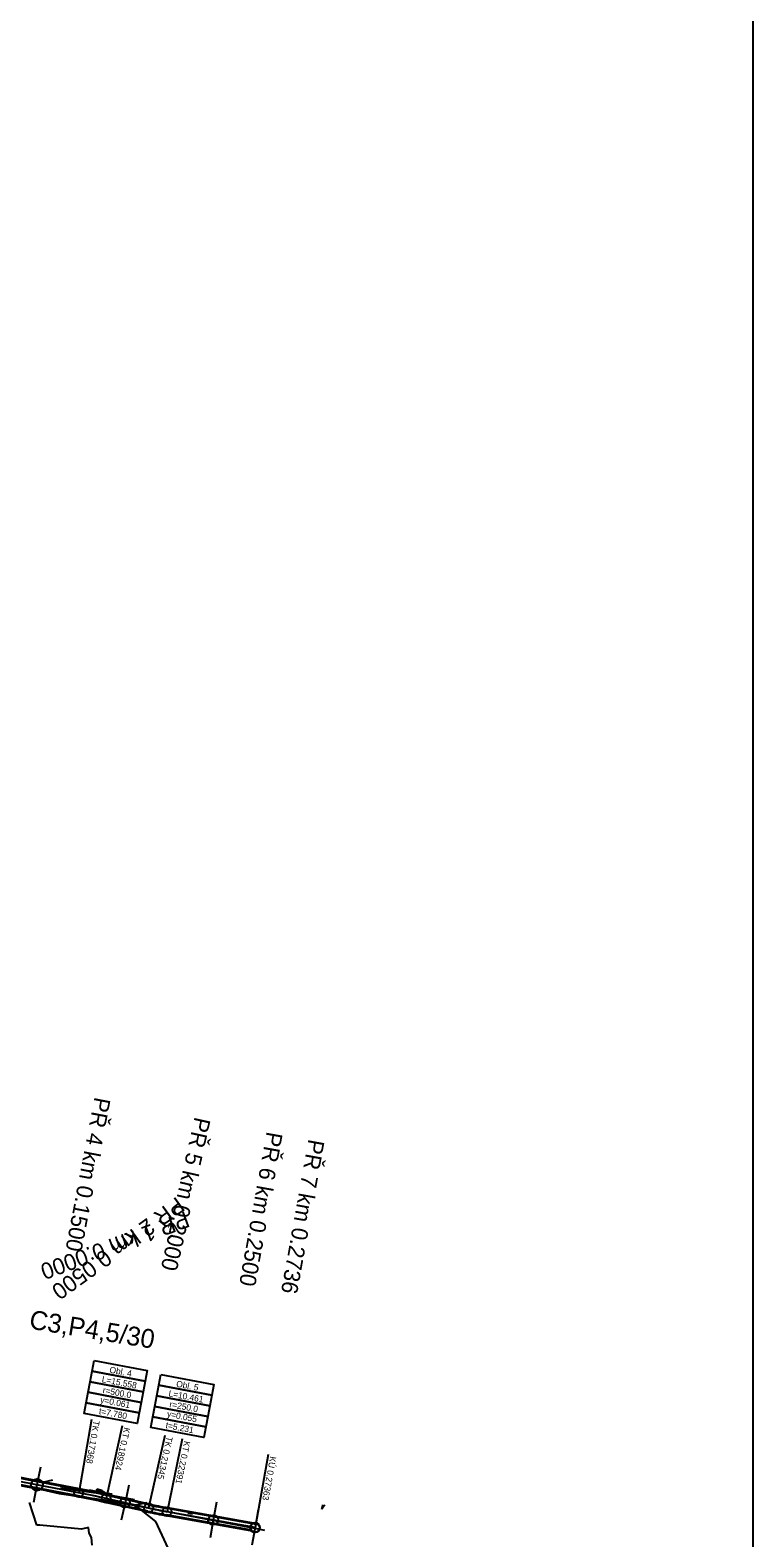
# Model space of a CAD drawing. Extents: x -549394 to -546608, y -1037055 to -1033629.
# Drawn here: x -547010 to -546608, y -1035815 to -1034976 of the extents above; entities that cross this region are included whole.
import ezdxf

# ---------------------------------------------------------------- set-up
doc = ezdxf.new("R2010")
doc.units = 0
for name, color, linetype in [('hlavni_vrst', 7, 'Continuous'), ('hrana_L', 7, 'Continuous'), ('norm_vrst', 7, 'Continuous'), ('POLYGONY_SITUACE_PO', 7, 'Continuous'), ('ram', 7, 'Continuous'), ('u_sirka_0_5m', 7, 'Continuous'), ('u_sirka_1_0m', 7, 'Continuous'), ('x_navrh_C3', 7, 'Continuous'), ('x_osa_C3', 7, 'Continuous'), ('x_popis_oblouky_C3', 7, 'Continuous'), ('x_popis_pricne_rezy_C3', 7, 'Continuous'), ('x_popis_velky_C3', 7, 'Continuous')]:
    doc.layers.add(name, color=color, linetype=linetype)

msp = doc.modelspace()

# ---------------------------------------------------------------- linework, layer by layer
at = {"layer": 'hlavni_vrst'}
for p, q in [((-547006.35, -1035807.78), (-547010.39, -1035795.15)), ((-547004.64, -1035807.74), (-547006.35, -1035807.78)), ((-546981.44, -1035810.13), (-547004.64, -1035807.74)), ((-546977.6, -1035809.03), (-546981.44, -1035810.13)), ((-546977.2, -1035812.22), (-546977.6, -1035809.03)), ((-546975.87, -1035814.66), (-546977.2, -1035812.22)), ((-546975.65, -1035818.99), (-546975.87, -1035814.66))]:
    msp.add_line(p, q, dxfattribs=at)
at = {"layer": 'hrana_L'}
for p, q in [((-547014.03, -1035785.6), (-546993.98, -1035790.12)), ((-546968.09, -1035790.83), (-546993.14, -1035787.24)), ((-546993.98, -1035790.12), (-546968.85, -1035793.8)), ((-546968.85, -1035793.8), (-546952.42, -1035796.77)), ((-546952.1, -1035793.78), (-546968.09, -1035790.83)), ((-546952.42, -1035796.77), (-546883.17, -1035809.84)), ((-546883.17, -1035809.84), (-546879.7, -1035810.51))]:
    msp.add_line(p, q, dxfattribs=at)
at = {"layer": 'norm_vrst'}
for p, q in [((-547006.15, -1035783.3), (-547005.9, -1035783.02)), ((-547003.25, -1035784.08), (-547006.15, -1035783.3)), ((-546997.72, -1035782.74), (-547003.25, -1035784.08)), ((-546970.81, -1035789.67), (-546977.11, -1035788.3)), ((-546973.1, -1035788.18), (-546973.24, -1035788.47)), ((-546973.06, -1035787.84), (-546973.1, -1035788.18)), ((-546970.15, -1035788.45), (-546973.06, -1035787.84)), ((-546968.54, -1035789.66), (-546970.15, -1035788.45)), ((-546973.24, -1035788.47), (-546968.54, -1035789.66)), ((-546968.54, -1035789.66), (-546970.81, -1035789.67)), ((-546968.18, -1035789.94), (-546968.54, -1035789.66)), ((-546964.44, -1035790.6), (-546968.18, -1035789.94)), ((-546955.59, -1035796.11), (-546955.59, -1035796.11)), ((-546955.59, -1035796.11), (-546955.59, -1035796.11)), ((-546955.59, -1035796.11), (-546955.59, -1035796.11)), ((-546952.42, -1035796.77), (-546944.99, -1035795.23)), ((-546952.42, -1035796.77), (-546952.42, -1035796.77)), ((-546952.42, -1035796.77), (-546952.42, -1035796.77)), ((-546952.42, -1035796.77), (-546952.42, -1035796.77)), ((-546952.42, -1035796.77), (-546952.42, -1035796.77)), ((-546948.22, -1035799.39), (-546952.42, -1035796.77)), ((-546952.42, -1035796.77), (-546952.42, -1035796.77)), ((-546952.42, -1035796.77), (-546952.42, -1035796.77)), ((-546952.42, -1035796.77), (-546952.42, -1035796.77)), ((-546847.88, -1035798.82), (-546847.2, -1035796.64)), ((-546847.2, -1035796.64), (-546847.18, -1035796.51)), ((-546846.06, -1035796.69), (-546846.65, -1035797.25)), ((-546940.13, -1035805.7), (-546948.22, -1035799.39)), ((-546922.27, -1035801.2), (-546919.68, -1035801.42)), ((-546846.65, -1035797.25), (-546847.88, -1035798.82)), ((-546927.47, -1035833.03), (-546940.13, -1035805.7))]:
    msp.add_line(p, q, dxfattribs=at)
at = {"layer": 'POLYGONY_SITUACE_PO'}
for centre in [(-546983.03, -1035789.81), (-546967.79, -1035792.97), (-546944.17, -1035798.25), (-546933.91, -1035800.32), (-546884.98, -1035809.13)]:
    msp.add_circle(centre, 2.5, dxfattribs=at)
at = {"layer": 'ram'}
msp.add_lwpolyline([(-549394.28, -1037054.81), (-549394.28, -1033629.11), (-546608.04, -1033629.11), (-546608.04, -1037054.81), (-549394.28, -1037054.81)], dxfattribs=at)
at = {"layer": 'u_sirka_0_5m'}
for centre in [(-546957.3, -1035795.32), (-546908.24, -1035804.94), (-546884.98, -1035809.13)]:
    msp.add_circle(centre, 2.75, dxfattribs=at)
at = {"layer": 'u_sirka_1_0m'}
msp.add_circle((-547006.29, -1035785.36), 3.25, dxfattribs=at)
at = {"layer": 'x_navrh_C3'}
for p, q in [((-546983.36, -1035791.53), (-547022.05, -1035784.13)), ((-546982.7, -1035788.09), (-547021.39, -1035780.7)), ((-546944.55, -1035799.96), (-546968.18, -1035794.68)), ((-546943.78, -1035796.54), (-546967.41, -1035791.26)), ((-546886.73, -1035810.59), (-546934.22, -1035802.04)), ((-546883.23, -1035807.67), (-546933.6, -1035798.6))]:
    msp.add_line(p, q, dxfattribs=at)
for points in [[(-546983.45, -1035792.02), (-547022.14, -1035784.63)], [(-546982.61, -1035787.6), (-547021.3, -1035780.21)], [(-546944.66, -1035800.45), (-546968.29, -1035795.17)], [(-546943.68, -1035796.06), (-546967.3, -1035790.77)], [(-546885.38, -1035811.35), (-546934.31, -1035802.54)], [(-546882.74, -1035807.25), (-546933.52, -1035798.11)]]:
    msp.add_lwpolyline(points, dxfattribs=at)
for centre, radius, start, end in [((-547076.9, -1036280.92), 501.75, 77.39607, 79.17893), ((-547076.9, -1036280.92), 502.25, 77.39607, 79.17893), ((-547076.9, -1036280.92), 497.75, 77.39607, 79.17893), ((-547076.9, -1036280.92), 498.25, 77.39607, 79.17893), ((-546889.61, -1035554.28), 248.25, 257.39607, 259.79358), ((-546889.61, -1035554.28), 247.75, 257.39607, 259.79358), ((-546889.61, -1035554.28), 252.25, 257.39607, 259.79358), ((-546889.61, -1035554.28), 251.75, 257.39607, 259.79358)]:
    msp.add_arc(centre, radius, start, end, dxfattribs=at)
at = {"layer": 'x_osa_C3'}
msp.add_lwpolyline([(-546884.98, -1035809.13), (-546939.06, -1035799.39), (-546975.39, -1035791.27), (-547035.62, -1035779.76), (-547091.59, -1035774.45)], dxfattribs=at)
for centre, radius, start, end in [((-547076.9, -1036280.92), 500, 77.39607, 79.17893), ((-546889.61, -1035554.28), 250, 257.39607, 259.79358)]:
    msp.add_arc(centre, radius, start, end, dxfattribs=at)
at = {"layer": 'x_popis_oblouky_C3'}
for points in [[(-546974.47, -1035716.17), (-546944.99, -1035721.76), (-546946.11, -1035727.66), (-546975.59, -1035722.06)], [(-546976.7, -1035727.96), (-546947.23, -1035733.55), (-546948.35, -1035739.45), (-546977.82, -1035733.85)], [(-546975.59, -1035722.06), (-546946.11, -1035727.66), (-546947.23, -1035733.55), (-546976.7, -1035727.96)], [(-546937.35, -1035723.99), (-546907.87, -1035729.59), (-546908.99, -1035735.48), (-546938.47, -1035729.89)], [(-546977.82, -1035733.85), (-546948.35, -1035739.45), (-546949.47, -1035745.34), (-546978.94, -1035739.75)], [(-546939.58, -1035735.78), (-546910.11, -1035741.38), (-546911.23, -1035747.27), (-546940.7, -1035741.68)], [(-546938.47, -1035729.89), (-546908.99, -1035735.48), (-546910.11, -1035741.38), (-546939.58, -1035735.78)], [(-546978.94, -1035739.75), (-546949.47, -1035745.34), (-546950.59, -1035751.24), (-546980.06, -1035745.64)], [(-546940.7, -1035741.68), (-546911.23, -1035747.27), (-546912.35, -1035753.16), (-546941.82, -1035747.57)], [(-546941.82, -1035747.57), (-546912.35, -1035753.16), (-546913.47, -1035759.06), (-546942.94, -1035753.47)]]:
    msp.add_lwpolyline(points, close=True, dxfattribs=at)
for points in [[(-546976.02, -1035749.04), (-546983.03, -1035789.81)], [(-546958.81, -1035752.58), (-546967.79, -1035792.97)], [(-546935.18, -1035757.87), (-546944.17, -1035798.25)], [(-546925.53, -1035759.8), (-546933.91, -1035800.32)], [(-546877.66, -1035768.41), (-546884.98, -1035809.13)]]:
    msp.add_lwpolyline(points, dxfattribs=at)
at = {"layer": 'x_popis_pricne_rezy_C3'}
for points in [[(-547004.41, -1035775.54), (-547006.29, -1035785.36), (-547008.17, -1035795.19)], [(-546955.11, -1035785.56), (-546957.3, -1035795.32), (-546959.48, -1035805.08)], [(-546906.47, -1035795.1), (-546908.24, -1035804.94), (-546910.01, -1035814.79)], [(-546883.21, -1035799.29), (-546884.98, -1035809.13), (-546886.75, -1035818.97)]]:
    msp.add_lwpolyline(points, dxfattribs=at)

# ---------------------------------------------------------------- texts
at = {"layer": 'x_popis_oblouky_C3'}
for s, rotation, p in [('Obl. 4', 349.27723, (-546966.16, -1035722.89)), ('L=15.558', 349.27723, (-546970.43, -1035728.19)), ('Obl. 5', 349.27723, (-546929.04, -1035730.71)), ('y=0.061', 349.27723, (-546971.3, -1035739.61)), ('r=500.0', 349.27723, (-546969.91, -1035734.22)), ('L=10.461', 349.27723, (-546933.31, -1035736.01)), ('t=7.780', 349.27723, (-546972.02, -1035745.94)), ('y=0.055', 349.27723, (-546934.17, -1035747.44)), ('r=250.0', 349.27723, (-546932.79, -1035742.04)), ('TK 0.17368', 260.24686, (-546974.82, -1035749.38)), ('KT 0.18924', 257.45479, (-546957.76, -1035753.15)), ('t=5.231', 349.27723, (-546934.9, -1035753.76)), ('TK 0.21345', 257.45479, (-546934.12, -1035758.23)), ('KT 0.22391', 258.31652, (-546924.36, -1035760.73)), ('KÚ 0.27363', 259.8113, (-546876.57, -1035769.3))]:
    msp.add_text(s, height=3.5, rotation=rotation, dxfattribs=at).set_placement(p)
at = {"layer": 'x_popis_pricne_rezy_C3'}
for s, rotation, p in [('PŘ 4 km 0.1500', 259.17893, (-546974.18, -1035569.11)), ('PŘ 5 km 0.2000', 257.39607, (-546918.47, -1035580.16)), ('PŘ 6 km 0.2500', 259.79358, (-546878.45, -1035588.35)), ('PŘ 7 km 0.2736', 259.79358, (-546855.19, -1035592.54)), ('PŘ 2 km 0.0500', 215.87276, (-546928.55, -1035624.61)), ('PŘ 1 km 0.0000', 200.22189, (-546923.63, -1035632.86))]:
    msp.add_text(s, height=9.0627, rotation=rotation, dxfattribs=at).set_placement(p)
at = {"layer": 'x_popis_velky_C3'}
msp.add_text('C3,P4,5/30', height=10.5, rotation=350.69476, dxfattribs=at).set_placement((-547011.05, -1035698.28))

doc.saveas('drawing.dxf')
